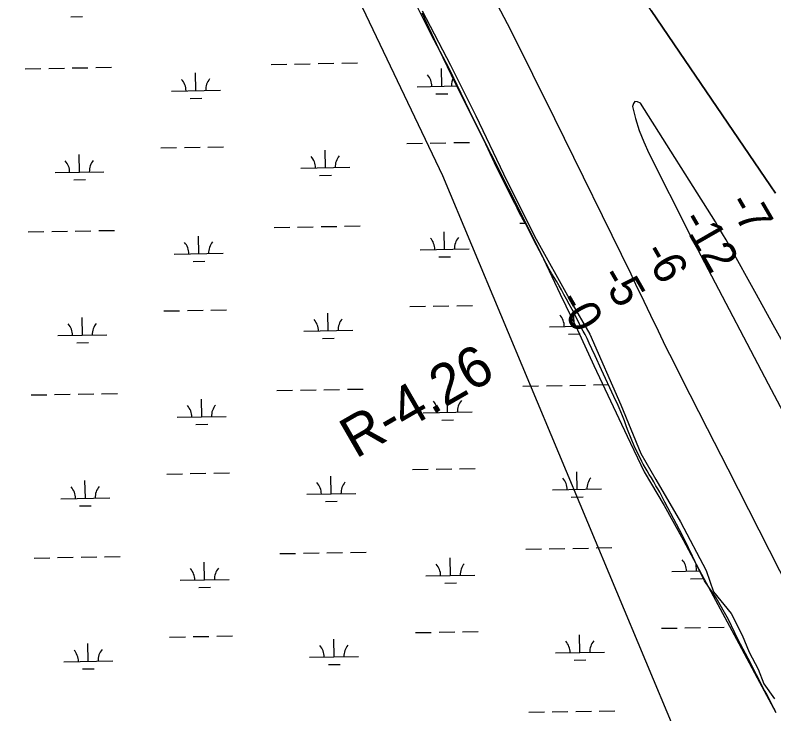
# Model space of a CAD drawing. Extents: x 3914892 to 3953151, y 242587 to 268572.
# Drawn here: x 3932544 to 3934093, y 261360 to 262785 of the extents above; entities that cross this region are included whole.
import ezdxf

# ---------------------------------------------------------------- set-up
doc = ezdxf.new("R2010")
doc.units = 0
for name, color, linetype in [('V-RIVR-EDGE', 7, 'Continuous'), ('V-RIVR-RANG', 7, 'Continuous'), ('V-RIVR-RANG-IDEN', 7, 'Continuous'), ('V-RRAP-FSHR', 7, 'Continuous'), ('V-SITE-VEGE', 7, 'Continuous'), ('V-TOPO-DPTH', 7, 'Continuous'), ('V-TOPO-MINR', 7, 'Continuous'), ('V-WETL-SWMP', 7, 'Continuous')]:
    doc.layers.add(name, color=color, linetype=linetype)

msp = doc.modelspace()

# ---------------------------------------------------------------- linework, layer by layer
at = {"layer": 'V-RIVR-EDGE'}
msp.add_lwpolyline([(3933375.4, 262793.6), (3933432.7, 262683), (3933484.9, 262579.7), (3933541.2, 262460.9), (3933604.7, 262334), (3933678.4, 262200.9), (3933717.3, 262134.3), (3933780.8, 261990), (3933821.7, 261890.7), (3933852.4, 261837.5), (3933902.6, 261751.5), (3933954.8, 261652.2), (3933970.1, 261608.2), (3934006, 261564.1), (3934028.5, 261520.1), (3934042.8, 261485.3), (3934061.3, 261450.5), (3934072.5, 261420.8), (3934094, 261390.1)], dxfattribs=at)
at = {"layer": 'V-RRAP-FSHR'}
msp.add_lwpolyline([(3933374.7, 262789.3), (3933408.6, 262716.9), (3933443.2, 262644.8), (3933479.3, 262573.4), (3933515.4, 262502), (3933551.5, 262430.6), (3933587.6, 262359.2), (3933622.8, 262287.4), (3933656.9, 262215.4), (3933692, 262142.7), (3933725.3, 262070.4), (3933759.4, 261998.3), (3933793.6, 261925.7), (3933828.2, 261853.6), (3933868.8, 261784.7), (3933907.7, 261714.8), (3933945.6, 261644.3), (3933983.4, 261573.8), (3934021.3, 261503.3), (3934059.1, 261432.9), (3934097, 261362.4)], dxfattribs=at)
at = {"layer": 'V-SITE-VEGE'}
msp.add_lwpolyline([(3934289.5, 260701.2), (3933891.1, 261325.9), (3933417.4, 262456.9), (3932954.5, 263426.4), (3932739.2, 263803.4), (3932470, 264137.3), (3932383.9, 264115.7), (3932383.9, 264051.1), (3932405.4, 263954.2), (3932383.9, 263911.1), (3932276.2, 264008), (3932190.1, 264245), (3932141.4, 264285.3)], dxfattribs=at)
at = {"layer": 'V-TOPO-DPTH'}
for points in [[(3934096.4, 262422), (3934086.3, 262436.7), (3933900.3, 262709.1), (3933842.4, 262794.4), (3933784.8, 262880), (3933727.8, 262965.9), (3933671.1, 263052), (3933579.1, 263192.9), (3933568.9, 263208.9), (3933558.9, 263225), (3933549.2, 263241.3), (3933539.8, 263257.8), (3933529.9, 263275.5)], [(3934126.2, 262091.1), (3934091.9, 262153.2), (3934057.5, 262215.2), (3934002.3, 262314.5), (3933995.4, 262326.7), (3933988.3, 262338.9), (3933981, 262350.9), (3933973.6, 262362.9), (3933820.5, 262605.1), (3933814.4, 262608.2), (3933809.5, 262608.6), (3933806.3, 262604.8), (3933804.2, 262598.4), (3933810.5, 262573.9), (3933818, 262549.8), (3933827.3, 262526.4), (3933837.8, 262503.4), (3933921.6, 262337.7), (3933928.9, 262323.2), (3933936.3, 262308.8), (3933943.8, 262294.4), (3933951.3, 262280), (3934081.3, 262032.6), (3934137, 261927.1)]]:
    msp.add_lwpolyline(points, dxfattribs=at)
at = {"layer": 'V-TOPO-MINR'}
for points in [[(3933508.8, 262844.5), (3933555.2, 262754.8), (3933600.7, 262664.7), (3933645.6, 262574.3), (3933800.8, 262256.9), (3933805.8, 262246.6), (3933810.8, 262236.4), (3933815.7, 262226.1), (3933820.7, 262215.8), (3933841.3, 262172.6), (3933856.6, 262140.7), (3933872.1, 262108.9), (3933887.9, 262077.3), (3933903.9, 262045.8), (3933956.9, 261941.8), (3933999.2, 261859.1), (3934041.5, 261776.3), (3934083.7, 261693.6), (3934125.9, 261610.8)], [(3933842.4, 262794.4), (3933900.3, 262709.1), (3934086.3, 262436.7), (3934096.4, 262422)], [(3934126.2, 262091.1), (3934091.9, 262153.2), (3934057.5, 262215.2), (3934002.3, 262314.5), (3933995.4, 262326.7), (3933988.3, 262338.9), (3933981, 262350.9), (3933973.6, 262362.9), (3933820.5, 262605.1), (3933814.4, 262608.2), (3933809.5, 262608.6), (3933806.3, 262604.8), (3933804.2, 262598.4), (3933810.5, 262573.9), (3933818, 262549.8), (3933827.3, 262526.4), (3933837.8, 262503.4), (3933921.6, 262337.7), (3933928.9, 262323.2), (3933936.3, 262308.8), (3933943.8, 262294.4), (3933951.3, 262280), (3934081.3, 262032.6), (3934137, 261927.1)]]:
    msp.add_lwpolyline(points, dxfattribs=at)
at = {"layer": 'V-WETL-SWMP'}
for p, q in [((3932658.1, 262781.6), (3932682.1, 262782.1)), ((3933114.9, 262685.1), (3933146.9, 262685.7)), ((3933162.9, 262686), (3933194.9, 262686.6)), ((3933210.9, 262686.9), (3933242.9, 262687.4)), ((3932565.1, 262675.3), (3932597.1, 262675.9)), ((3932613.1, 262676.2), (3932645.1, 262676.7)), ((3932661.1, 262677), (3932693.1, 262677.6)), ((3932709.1, 262677.9), (3932741.1, 262678.5)), ((3933066.9, 262684.3), (3933098.9, 262684.9)), ((3933415.1, 262639.8), (3933414.5, 262675.8)), ((3932913.3, 262630.8), (3932912.6, 262666.8)), ((3933365.1, 262638.9), (3933447.5, 262640.3)), ((3932863.3, 262629.9), (3932963.3, 262631.7)), ((3933403.4, 262624.1), (3933427.4, 262624.6)), ((3932901.6, 262615.1), (3932925.6, 262615.6)), ((3932889.9, 262514.9), (3932921.9, 262515.5)), ((3932937.9, 262515.8), (3932969.9, 262516.4)), ((3933343.8, 262523), (3933375.8, 262523.6)), ((3933391.8, 262523.9), (3933423.8, 262524.5)), ((3933439.8, 262524.8), (3933471.8, 262525.3)), ((3932675.7, 262464.7), (3932675.1, 262500.6)), ((3932842, 262514.1), (3932874, 262514.6)), ((3933177.6, 262473.6), (3933176.9, 262509.6)), ((3933127.6, 262472.7), (3933227.6, 262474.5)), ((3932625.8, 262463.8), (3932725.7, 262465.5)), ((3933165.9, 262458), (3933189.9, 262458.4)), ((3932664, 262449), (3932688, 262449.4)), ((3933574.7, 262360.6), (3933585.5, 262360.8)), ((3932667.1, 262344.4), (3932699.1, 262345)), ((3932715, 262345.3), (3932747, 262345.8)), ((3933072.9, 262351.7), (3933104.9, 262352.2)), ((3933120.9, 262352.5), (3933152.9, 262353.1)), ((3933168.9, 262353.4), (3933200.9, 262354)), ((3933216.9, 262354.2), (3933248.9, 262354.8)), ((3932571.1, 262342.7), (3932603.1, 262343.3)), ((3932619.1, 262343.5), (3932651.1, 262344.1)), ((3932919.2, 262298.2), (3932918.6, 262334.2)), ((3933421.1, 262307.1), (3933420.4, 262343.1)), ((3932869.2, 262297.3), (3932969.2, 262299.1)), ((3933371.1, 262306.3), (3933471.1, 262308)), ((3932907.5, 262282.5), (3932931.5, 262283)), ((3933409.3, 262291.5), (3933433.3, 262291.9)), ((3933349.7, 262190.4), (3933381.7, 262191)), ((3933397.7, 262191.3), (3933429.7, 262191.9)), ((3933445.7, 262192.1), (3933477.7, 262192.7)), ((3932847.9, 262181.4), (3932879.9, 262182)), ((3932895.9, 262182.3), (3932927.9, 262182.9)), ((3932943.9, 262183.2), (3932975.9, 262183.7)), ((3933183.5, 262141), (3933182.9, 262177)), ((3933685.4, 262150), (3933684.9, 262178.2)), ((3932681.7, 262132), (3932681.1, 262168)), ((3933635.4, 262149.1), (3933699.1, 262150.2)), ((3932631.7, 262131.1), (3932731.7, 262132.9)), ((3933133.5, 262140.1), (3933233.5, 262141.9)), ((3933673.6, 262134.3), (3933697.6, 262134.8)), ((3932670, 262116.4), (3932694, 262116.8)), ((3933171.8, 262125.4), (3933195.8, 262125.8)), ((3933078.8, 262019), (3933110.8, 262019.6)), ((3933126.8, 262019.9), (3933158.8, 262020.5)), ((3933174.8, 262020.8), (3933206.8, 262021.3)), ((3933222.8, 262021.6), (3933254.8, 262022.2)), ((3933580.7, 262028), (3933612.7, 262028.6)), ((3933628.7, 262028.9), (3933660.7, 262029.5)), ((3933676.7, 262029.7), (3933708.7, 262030.3)), ((3933724.7, 262030.6), (3933755.2, 262031.1)), ((3932577, 262010.1), (3932609, 262010.6)), ((3932625, 262010.9), (3932657, 262011.5)), ((3932673, 262011.8), (3932705, 262012.4)), ((3932721, 262012.6), (3932753, 262013.2)), ((3933427, 261974.5), (3933426.4, 262010.5)), ((3932925.2, 261965.5), (3932924.5, 262001.5)), ((3933377, 261973.6), (3933477, 261975.4)), ((3932875.2, 261964.7), (3932975.2, 261966.4)), ((3933415.3, 261958.9), (3933439.3, 261959.3)), ((3932913.5, 261949.9), (3932937.5, 261950.3)), ((3932853.9, 261848.8), (3932885.9, 261849.4)), ((3932901.9, 261849.7), (3932933.8, 261850.3)), ((3932949.8, 261850.5), (3932981.8, 261851.1)), ((3933355.7, 261857.8), (3933387.7, 261858.4)), ((3933403.7, 261858.7), (3933435.7, 261859.2)), ((3933451.7, 261859.5), (3933483.7, 261860.1)), ((3933691.3, 261817.4), (3933690.7, 261853.4)), ((3932687.7, 261799.4), (3932687, 261835.4)), ((3933189.5, 261808.4), (3933188.8, 261844.4)), ((3933641.3, 261816.5), (3933741.3, 261818.3)), ((3933139.5, 261807.5), (3933239.5, 261809.3)), ((3932637.7, 261798.5), (3932737.6, 261800.3)), ((3933177.8, 261792.7), (3933201.8, 261793.2)), ((3933679.6, 261801.7), (3933703.6, 261802.2)), ((3932675.9, 261783.8), (3932699.9, 261784.2)), ((3933586.6, 261695.4), (3933618.6, 261696)), ((3933634.6, 261696.3), (3933666.6, 261696.8)), ((3933682.6, 261697.1), (3933714.6, 261697.7)), ((3933730.6, 261698), (3933762.6, 261698.6)), ((3932631, 261678.3), (3932663, 261678.9)), ((3932679, 261679.2), (3932711, 261679.7)), ((3932727, 261680), (3932758.9, 261680.6)), ((3933084.8, 261686.4), (3933116.8, 261687)), ((3933132.8, 261687.3), (3933164.8, 261687.9)), ((3933180.8, 261688.1), (3933212.8, 261688.7)), ((3933228.8, 261689), (3933260.8, 261689.6)), ((3932583, 261677.4), (3932615, 261678)), ((3932931.1, 261632.9), (3932930.5, 261668.9)), ((3933433, 261641.9), (3933432.3, 261677.9)), ((3933934.8, 261650.9), (3933934.5, 261665.5)), ((3933884.8, 261650), (3933941.4, 261651)), ((3932881.1, 261632), (3932981.1, 261633.8)), ((3933383, 261641), (3933483, 261642.8)), ((3933923.1, 261635.2), (3933947.1, 261635.7)), ((3932919.4, 261617.3), (3932943.4, 261617.7)), ((3933421.2, 261626.3), (3933445.2, 261626.7)), ((3933361.6, 261525.2), (3933393.6, 261525.7)), ((3933409.6, 261526), (3933441.6, 261526.6)), ((3933457.6, 261526.9), (3933489.6, 261527.5)), ((3933863.5, 261534.2), (3933895.5, 261534.7)), ((3933911.5, 261535), (3933943.5, 261535.6)), ((3933959.4, 261535.9), (3933991.4, 261536.4)), ((3932859.8, 261516.2), (3932891.8, 261516.8)), ((3932907.8, 261517.1), (3932939.8, 261517.6)), ((3932955.8, 261517.9), (3932987.8, 261518.5)), ((3933195.4, 261475.8), (3933194.8, 261511.8)), ((3933697.3, 261484.7), (3933696.6, 261520.7)), ((3932693.6, 261466.8), (3932693, 261502.8)), ((3933647.3, 261483.8), (3933747.3, 261485.6)), ((3932643.6, 261465.9), (3932743.6, 261467.7)), ((3933145.4, 261474.9), (3933245.4, 261476.7)), ((3933685.5, 261469.1), (3933709.5, 261469.5)), ((3932681.9, 261451.1), (3932705.9, 261451.6)), ((3933183.7, 261460.1), (3933207.7, 261460.6)), ((3933592.6, 261362.8), (3933624.6, 261363.4)), ((3933640.6, 261363.6), (3933672.6, 261364.2)), ((3933688.6, 261364.5), (3933720.6, 261365.1)), ((3933736.6, 261365.4), (3933768.6, 261365.9))]:
    msp.add_line(p, q, dxfattribs=at)
msp.add_lwpolyline([(3934095.7, 261366.2), (3934090.3, 261376.1), (3934086.1, 261384.6), (3934082.2, 261392.8), (3934078.5, 261399.6), (3934074.2, 261407.5), (3934040.8, 261472.3), (3934019.7, 261511.8), (3934000.3, 261552), (3933975.3, 261596.1), (3933951.8, 261630.6), (3933943.7, 261646.3), (3933937.9, 261658.3), (3933927.1, 261681.2), (3933922.9, 261689.8), (3933918.7, 261698.4), (3933914, 261708.1), (3933909.9, 261716.6), (3933906.7, 261723.3), (3933870.6, 261791.5), (3933860.3, 261811.6), (3933856.2, 261818.7), (3933852.4, 261825), (3933847.9, 261832.8), (3933843.1, 261840.7), (3933838.6, 261848), (3933834.1, 261855.5), (3933830.3, 261862.2), (3933826.6, 261868.9), (3933823.6, 261874.6), (3933808, 261906.4), (3933795.9, 261936), (3933792.4, 261945.1), (3933787.9, 261957.1), (3933784, 261967.7), (3933780.5, 261975.6), (3933777.2, 261983.5), (3933772.9, 261993.2), (3933769.4, 262000.6), (3933766.3, 262006.7), (3933741.5, 262061.3), (3933728.3, 262089.7), (3933721.7, 262104.1), (3933716.3, 262115.7), (3933712, 262124.9), (3933707.6, 262133.6), (3933704.1, 262140.4), (3933681.6, 262184.5), (3933675.5, 262195.3), (3933670.1, 262205.5), (3933664.4, 262215.3), (3933659.4, 262224.3), (3933654.5, 262232.8), (3933649.3, 262242.1), (3933644.6, 262249.6), (3933639.9, 262257.3), (3933634.3, 262266.8), (3933608.7, 262315.3), (3933586.3, 262359.5), (3933579.4, 262371.5), (3933574.1, 262380.8), (3933568.9, 262390.8), (3933564.4, 262400.6), (3933527.8, 262473.2), (3933504.9, 262521.4), (3933480.3, 262572.7), (3933430.2, 262675.9), (3933393.7, 262745.4), (3933374.7, 262783.5), (3933363.2, 262806.4)], dxfattribs=at)
for centre, start, end in [((3932968.5, 262632.3), 140.2532, 181.7968), ((3933359.9, 262639.3), 0.2532, 41.7968), ((3933470.3, 262641.2), 152.4126, 181.7968), ((3932858, 262630.3), 0.2532, 41.7968), ((3932620.5, 262464.1), 0.2532, 41.7968), ((3932731, 262466.1), 140.2532, 181.7968), ((3933122.3, 262473.1), 0.2532, 41.7968), ((3933232.8, 262475.1), 140.2532, 181.7968), ((3933365.8, 262306.6), 0.2532, 41.7968), ((3933476.3, 262308.6), 140.2532, 181.7968), ((3932864, 262297.7), 0.2532, 41.7968), ((3932974.5, 262299.6), 140.2532, 181.7968), ((3933128.3, 262140.5), 0.2532, 41.7968), ((3933238.8, 262142.5), 140.2532, 181.7968), ((3933630.1, 262149.5), 0.2532, 41.7968), ((3932626.5, 262131.5), 0.2532, 41.7968), ((3932736.9, 262133.5), 140.2532, 181.7968), ((3932869.9, 261965), 0.2532, 41.7968), ((3932980.4, 261967), 140.2532, 181.7968), ((3933371.8, 261974), 0.2532, 41.7968), ((3933482.2, 261976), 140.2532, 181.7968), ((3933636.1, 261816.9), 0.2532, 41.7968), ((3933746.5, 261818.8), 140.2532, 181.7968), ((3932632.4, 261798.9), 0.2532, 41.7968), ((3932742.9, 261800.9), 140.2532, 181.7968), ((3933134.2, 261807.9), 0.2532, 41.7968), ((3933244.7, 261809.8), 140.2532, 181.7968), ((3933377.7, 261641.4), 0.2532, 41.7968), ((3933488.2, 261643.4), 140.2532, 181.7968), ((3933879.6, 261650.4), 0.2532, 41.7968), ((3932875.9, 261632.4), 0.2532, 41.7968), ((3932986.4, 261634.4), 140.2532, 181.7968), ((3933752.5, 261486.2), 140.2532, 181.7968), ((3933140.2, 261475.3), 0.2532, 41.7968), ((3933250.7, 261477.2), 140.2532, 181.7968), ((3933642, 261484.2), 0.2532, 41.7968), ((3932638.4, 261466.3), 0.2532, 41.7968), ((3932748.8, 261468.2), 140.2532, 181.7968)]:
    msp.add_arc(centre, 35.2, start, end, dxfattribs=at)

# ---------------------------------------------------------------- texts
at = {"layer": 'V-RIVR-RANG'}
for s, rotation, p in [('-7', 300.1379, (3933997.1, 262401)), ('-12', 299.8583, (3933901.8, 262366.6)), ('-6', 299.8583, (3933824.1, 262301.1)), ('-5', 299.8583, (3933736.7, 262252.5)), ('-0', 299.8583, (3933650.5, 262201.8))]:
    msp.add_text(s, height=67, rotation=rotation, dxfattribs=at).set_placement(p)
at = {"layer": 'V-RIVR-RANG-IDEN'}
msp.add_text('R-4.26', height=83, rotation=29.9963, dxfattribs=at).set_placement((3933239.6, 261879.2))

doc.saveas('drawing.dxf')
